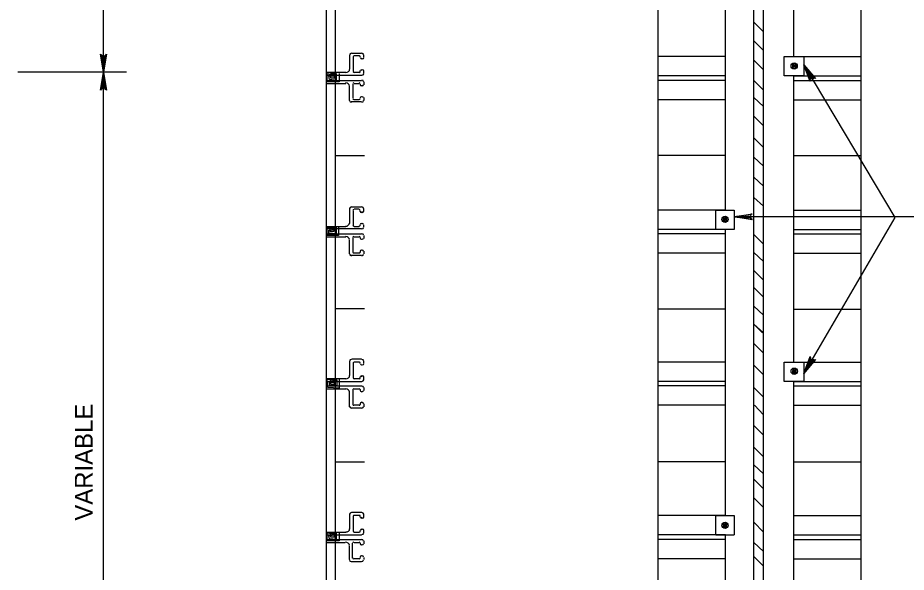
# Model space of a CAD drawing. Extents: x 647822 to 648727, y 298458 to 299646.
# Drawn here: x 648132.9 to 648281.8, y 299392.4 to 299485.4 of the extents above; entities that cross this region are included whole.
import ezdxf

# ---------------------------------------------------------------- set-up
doc = ezdxf.new("R2010")
doc.units = 0
doc.layers.add('2', color=7, linetype='Continuous')
doc.layers.add('3', color=7, linetype='Continuous')

# ---------------------------------------------------------------- blocks, each defined once
blk = doc.blocks.new('RARROW')
at = {"layer": '3'}
blk.add_lwpolyline([(-2.2695, 0.285), (-2.184875, 0.12075), (0, 0), (-2.2695, 0.285), (-2.38575, 0.384625), (0, 0), (-2.183125, -0.108), (-2.262875, -0.2705), (0, 0), (-2.38575, -0.379125), (-2.262875, -0.2705)], dxfattribs=at)

msp = doc.modelspace()

# ---------------------------------------------------------------- linework, layer by layer
at = {"layer": '2'}
for p, q in [((648147.25, 299476.23), (648147.25, 299540.48)), ((648184.63, 299335.43), (648184.63, 299539.1)), ((648186.13, 299335.43), (648186.13, 299539.1)), ((648240.25, 299335.47), (648240.25, 299538.73)), ((648256.25, 299335.47), (648256.25, 299538.73)), ((648257.88, 299335.47), (648257.88, 299538.73)), ((648274.25, 299335.47), (648274.25, 299538.73)), ((648263, 299478.85), (648263, 299522.23)), ((648251.5, 299453.1), (648251.5, 299500.6)), ((648257.88, 299482.98), (648256.25, 299484.6)), ((648257.88, 299479.85), (648256.25, 299481.48)), ((648188.5, 299479.1), (648188.5, 299476.73)), ((648190.5, 299479.35), (648188.88, 299479.35)), ((648189.13, 299478.85), (648189.13, 299476.35)), ((648190.13, 299478.98), (648189.25, 299478.98)), ((648190.25, 299478.73), (648190.25, 299478.85)), ((648190.63, 299478.48), (648190.5, 299478.48)), ((648190.88, 299478.73), (648190.88, 299479.1)), ((648251.5, 299478.85), (648240.25, 299478.85)), ((648257.88, 299476.6), (648256.25, 299478.23)), ((648261.38, 299478.85), (648264.63, 299478.85)), ((648261.38, 299475.6), (648261.38, 299478.85)), ((648263, 299478.85), (648274.25, 299478.85)), ((648263, 299478.85), (648263, 299478.85)), ((648264.63, 299478.85), (648264.63, 299475.6)), ((648190.25, 299476.35), (648190.25, 299476.48)), ((648190.5, 299476.6), (648190.63, 299476.6)), ((648190.88, 299475.98), (648190.88, 299476.48)), ((648264.63, 299477.48), (648279.88, 299451.85)), ((648151.13, 299476.23), (648132.88, 299476.23)), ((648147.25, 299335.48), (648147.25, 299476.23)), ((648184.63, 299476.23), (648187.88, 299476.23)), ((648184.63, 299475.73), (648190.5, 299475.73)), ((648189.25, 299476.23), (648190.13, 299476.23)), ((648251.5, 299475.6), (648240.25, 299475.6)), ((648264.63, 299475.6), (648261.38, 299475.6)), ((648263, 299475.73), (648263, 299475.73)), ((648263, 299475.6), (648274.25, 299475.6)), ((648263, 299427.6), (648263, 299475.6)), ((648184.63, 299474.85), (648190.5, 299474.85)), ((648184.63, 299474.35), (648187.88, 299474.35)), ((648188.5, 299471.48), (648188.5, 299473.85)), ((648189.13, 299471.85), (648189.13, 299474.23)), ((648189.25, 299474.35), (648190.13, 299474.35)), ((648190.25, 299474.23), (648190.25, 299474.1)), ((648190.5, 299473.98), (648190.63, 299473.98)), ((648190.88, 299474.6), (648190.88, 299474.1)), ((648251.5, 299474.85), (648240.25, 299474.85)), ((648257.88, 299473.23), (648256.25, 299474.85)), ((648263, 299474.85), (648274.25, 299474.85)), ((648190.25, 299471.98), (648190.25, 299471.85)), ((648190.63, 299472.1), (648190.5, 299472.1)), ((648190.88, 299471.98), (648190.88, 299471.48)), ((648257.88, 299470.48), (648256.25, 299471.98)), ((648190.5, 299471.23), (648188.75, 299471.23)), ((648190.13, 299471.6), (648189.25, 299471.6)), ((648251.5, 299471.6), (648240.25, 299471.6)), ((648263, 299471.6), (648274.25, 299471.6)), ((648257.88, 299467.23), (648256.25, 299468.85)), ((648257.88, 299463.6), (648256.25, 299465.23)), ((648186.13, 299462.23), (648191, 299462.23)), ((648251.5, 299462.23), (648240.25, 299462.23)), ((648257.88, 299460.48), (648256.25, 299461.98)), ((648263, 299462.23), (648274.25, 299462.23)), ((648257.88, 299457.1), (648256.25, 299458.6)), ((648257.88, 299453.73), (648256.25, 299455.23)), ((648188.5, 299453.35), (648188.5, 299450.85)), ((648190.5, 299453.6), (648188.75, 299453.6)), ((648189.13, 299452.98), (648189.13, 299450.48)), ((648190.13, 299453.23), (648189.25, 299453.23)), ((648190.25, 299452.85), (648190.25, 299452.98)), ((648190.63, 299452.73), (648190.5, 299452.73)), ((648190.88, 299452.85), (648190.88, 299453.35)), ((648251.5, 299453.1), (648240.25, 299453.1)), ((648249.88, 299453.1), (648253, 299453.1)), ((648249.88, 299449.85), (648249.88, 299453.1)), ((648251.5, 299453.1), (648251.5, 299453.1)), ((648253, 299453.1), (648253, 299449.85)), ((648263, 299453.1), (648274.25, 299453.1)), ((648280.13, 299451.98), (648253, 299451.98)), ((648279.88, 299451.85), (648264.63, 299425.69)), ((648313.17, 299451.98), (648279.88, 299451.98)), ((648184.63, 299450.35), (648187.88, 299450.35)), ((648184.63, 299449.98), (648190.5, 299449.98)), ((648189.25, 299450.35), (648190.13, 299450.35)), ((648190.25, 299450.48), (648190.25, 299450.6)), ((648190.5, 299450.85), (648190.63, 299450.85)), ((648190.88, 299450.23), (648190.88, 299450.6)), ((648251.5, 299449.85), (648240.25, 299449.85)), ((648253, 299449.85), (648249.88, 299449.85)), ((648251.5, 299401.85), (648251.5, 299449.85)), ((648263, 299449.85), (648274.25, 299449.85)), ((648184.63, 299449.1), (648190.5, 299449.1)), ((648184.63, 299448.6), (648187.88, 299448.6)), ((648188.5, 299445.73), (648188.5, 299448.1)), ((648189.13, 299445.98), (648189.13, 299448.48)), ((648189.25, 299448.6), (648190.13, 299448.6)), ((648190.25, 299448.48), (648190.25, 299448.35)), ((648190.5, 299448.23), (648190.63, 299448.23)), ((648190.88, 299448.85), (648190.88, 299448.35)), ((648251.5, 299449.1), (648240.25, 299449.1)), ((648257.88, 299447.35), (648256.25, 299448.98)), ((648263, 299449.1), (648274.25, 299449.1)), ((648190.5, 299445.48), (648188.75, 299445.48)), ((648190.13, 299445.85), (648189.25, 299445.85)), ((648190.25, 299446.23), (648190.25, 299445.98)), ((648190.63, 299446.35), (648190.5, 299446.35)), ((648190.88, 299446.23), (648190.88, 299445.73)), ((648251.5, 299445.85), (648240.25, 299445.85)), ((648257.88, 299444.48), (648256.25, 299445.98)), ((648263, 299445.85), (648274.25, 299445.85)), ((648257.88, 299441.35), (648256.25, 299442.98)), ((648257.88, 299438.48), (648256.25, 299440.1)), ((648186.13, 299436.6), (648191, 299436.6)), ((648251.5, 299436.48), (648240.25, 299436.48)), ((648257.88, 299435.48), (648256.25, 299436.98)), ((648263, 299436.48), (648274.25, 299436.48)), ((648257.75, 299432.48), (648256.25, 299433.98)), ((648257.88, 299432.48), (648256.25, 299433.98)), ((648257.88, 299429.1), (648256.25, 299430.73)), ((648188.5, 299427.73), (648188.5, 299425.35)), ((648190.5, 299428.1), (648188.88, 299428.1)), ((648189.13, 299427.48), (648189.13, 299424.98)), ((648190.13, 299427.6), (648189.25, 299427.6)), ((648190.25, 299427.35), (648190.25, 299427.48)), ((648190.88, 299427.35), (648190.88, 299427.73)), ((648251.38, 299427.6), (648240.25, 299427.6)), ((648261.38, 299427.6), (648264.63, 299427.6)), ((648261.38, 299424.35), (648261.38, 299427.6)), ((648263, 299427.6), (648274.25, 299427.6)), ((648264.63, 299427.6), (648264.63, 299424.35)), ((648190.63, 299427.1), (648190.5, 299427.1)), ((648257.88, 299425.48), (648256.25, 299427.1)), ((648184.63, 299424.85), (648187.88, 299424.85)), ((648184.63, 299424.35), (648190.5, 299424.35)), ((648189.25, 299424.85), (648190.13, 299424.85)), ((648190.25, 299424.98), (648190.25, 299425.1)), ((648190.5, 299425.23), (648190.63, 299425.23)), ((648190.88, 299424.6), (648190.88, 299425.1)), ((648251.38, 299424.35), (648240.25, 299424.35)), ((648264.63, 299424.35), (648261.38, 299424.35)), ((648263, 299424.35), (648274.25, 299424.35)), ((648263, 299376.1), (648263, 299424.35)), ((648184.63, 299423.6), (648190.5, 299423.6)), ((648184.63, 299423.1), (648187.88, 299423.1)), ((648189.13, 299420.48), (648189.13, 299422.98)), ((648189.25, 299423.1), (648190.13, 299423.1)), ((648190.25, 299422.98), (648190.25, 299422.85)), ((648190.88, 299423.35), (648190.88, 299422.85)), ((648251.38, 299423.6), (648240.25, 299423.6)), ((648257.88, 299421.73), (648256.25, 299423.35)), ((648263, 299423.6), (648274.25, 299423.6)), ((648188.5, 299420.1), (648188.5, 299422.6)), ((648190.5, 299422.6), (648190.63, 299422.6)), ((648190.5, 299419.85), (648188.75, 299419.85)), ((648190.13, 299420.35), (648189.25, 299420.35)), ((648190.25, 299420.6), (648190.25, 299420.48)), ((648190.63, 299420.85), (648190.5, 299420.85)), ((648190.88, 299420.6), (648190.88, 299420.1)), ((648251.38, 299420.35), (648240.25, 299420.35)), ((648257.88, 299418.73), (648256.38, 299420.35)), ((648263, 299420.35), (648274.25, 299420.35)), ((648257.88, 299415.35), (648256.25, 299416.98)), ((648257.88, 299411.73), (648256.25, 299413.35)), ((648186.13, 299410.85), (648191, 299410.85)), ((648251.5, 299410.85), (648240.25, 299410.85)), ((648263, 299410.85), (648274.25, 299410.85)), ((648257.88, 299408.85), (648256.25, 299410.35)), ((648257.88, 299406.35), (648256.25, 299407.98)), ((648257.88, 299403.23), (648256.25, 299404.85)), ((648188.5, 299402.1), (648188.5, 299399.6)), ((648190.5, 299402.35), (648188.88, 299402.35)), ((648190.88, 299401.6), (648190.88, 299402.1)), ((648189.13, 299401.73), (648189.13, 299399.23)), ((648190.13, 299401.85), (648189.25, 299401.85)), ((648190.25, 299401.6), (648190.25, 299401.73)), ((648190.63, 299401.48), (648190.5, 299401.48)), ((648251.5, 299401.85), (648240.25, 299401.85)), ((648249.88, 299401.85), (648253, 299401.85)), ((648249.88, 299398.6), (648249.88, 299401.85)), ((648251.5, 299401.85), (648251.5, 299401.85)), ((648253, 299401.85), (648253, 299398.6)), ((648257.88, 299399.1), (648256.25, 299400.73)), ((648263, 299401.85), (648274.25, 299401.85)), ((648184.63, 299399.1), (648187.88, 299399.1)), ((648189.25, 299399.1), (648190.13, 299399.1)), ((648190.25, 299399.23), (648190.25, 299399.35)), ((648190.5, 299399.6), (648190.63, 299399.6)), ((648190.88, 299398.98), (648190.88, 299399.35)), ((648184.63, 299398.6), (648190.5, 299398.6)), ((648184.63, 299397.85), (648190.5, 299397.85)), ((648190.88, 299397.6), (648190.88, 299397.1)), ((648251.5, 299398.6), (648240.25, 299398.6)), ((648251.5, 299397.85), (648240.25, 299397.85)), ((648251.5, 299398.6), (648249.88, 299398.6)), ((648249.88, 299398.6), (648253, 299398.6)), ((648251.5, 299398.6), (648251.5, 299398.6)), ((648251.5, 299352.1), (648251.5, 299398.6)), ((648263, 299398.6), (648274.25, 299398.6)), ((648263, 299397.85), (648274.25, 299397.85)), ((648184.63, 299397.35), (648187.75, 299397.35)), ((648188.5, 299394.48), (648188.5, 299396.85)), ((648189, 299394.73), (648189, 299397.23)), ((648189.25, 299397.35), (648190.13, 299397.35)), ((648190.25, 299397.23), (648190.25, 299397.1)), ((648190.5, 299396.98), (648190.63, 299396.98)), ((648257.88, 299395.85), (648256.25, 299397.35)), ((648190.13, 299394.6), (648189.25, 299394.6)), ((648190.25, 299394.85), (648190.25, 299394.73)), ((648190.63, 299395.1), (648190.5, 299395.1)), ((648190.88, 299394.85), (648190.88, 299394.48)), ((648251.5, 299394.6), (648240.25, 299394.6)), ((648257.88, 299393.35), (648256.25, 299394.98)), ((648263, 299394.6), (648274.25, 299394.6)), ((648190.5, 299394.1), (648188.75, 299394.1))]:
    msp.add_line(p, q, dxfattribs=at)
for points in [[(648262.88, 299477.6), (648262.75, 299477.35), (648262.75, 299476.98), (648263, 299476.85), (648263.25, 299476.98), (648263.38, 299477.23), (648263.38, 299477.48), (648263.25, 299477.6), (648263, 299477.6), (648262.88, 299477.35), (648262.88, 299477.23), (648262.88, 299477.1), (648263, 299477.1), (648263.13, 299477.23), (648263.25, 299477.35), (648263.13, 299477.48), (648263.13, 299477.35), (648263, 299477.23)], [(648186.75, 299475.98), (648186.75, 299474.6), (648184.75, 299474.6), (648184.75, 299475.98), (648186.25, 299475.73), (648186.25, 299475.85), (648186.25, 299474.85), (648185.13, 299474.98), (648185, 299475.6), (648185.88, 299475.6), (648186, 299475.23), (648185.38, 299475.23), (648185.38, 299475.98), (648186.25, 299475.98), (648186.25, 299475.85)], [(648251.25, 299451.85), (648251.13, 299451.6), (648251.13, 299451.35), (648251.38, 299451.1), (648251.63, 299451.23), (648251.75, 299451.48), (648251.75, 299451.73), (648251.63, 299451.85), (648251.5, 299451.85), (648251.25, 299451.6), (648251.25, 299451.48), (648251.25, 299451.35), (648251.38, 299451.35), (648251.5, 299451.48), (648251.63, 299451.6), (648251.63, 299451.73), (648251.5, 299451.6), (648251.38, 299451.48)], [(648186.63, 299450.23), (648186.63, 299448.85), (648184.75, 299448.85), (648184.75, 299450.23), (648186.25, 299449.98), (648186.25, 299450.1), (648186.25, 299449.1), (648185, 299449.23), (648185, 299449.73), (648185.88, 299449.85), (648185.88, 299449.48), (648185.25, 299449.48), (648185.25, 299450.23), (648186.25, 299450.23), (648186.25, 299450.1)], [(648262.88, 299426.48), (648262.75, 299426.1), (648262.75, 299425.85), (648263, 299425.73), (648263.25, 299425.73), (648263.38, 299425.98), (648263.38, 299426.23), (648263.25, 299426.48), (648263, 299426.35), (648262.88, 299426.1), (648262.88, 299425.98), (648262.88, 299425.85), (648263, 299425.85), (648263.13, 299425.98), (648263.25, 299426.1), (648263.13, 299426.23), (648263.13, 299426.1), (648263, 299425.98)], [(648186.75, 299424.73), (648186.75, 299423.23), (648184.88, 299423.35), (648184.75, 299424.73), (648186.25, 299424.48), (648186.38, 299424.6), (648186.38, 299423.6), (648185.13, 299423.6), (648185.13, 299424.23), (648185.88, 299424.23), (648186, 299423.85), (648185.38, 299423.85), (648185.38, 299424.73), (648186.25, 299424.73), (648186.25, 299424.48)], [(648251.25, 299400.6), (648251.13, 299400.23), (648251.13, 299399.98), (648251.38, 299399.85), (648251.63, 299399.98), (648251.75, 299400.23), (648251.75, 299400.48), (648251.63, 299400.6), (648251.5, 299400.48), (648251.25, 299400.23), (648251.25, 299400.1), (648251.25, 299400.1), (648251.38, 299399.98), (648251.5, 299400.23), (648251.63, 299400.23), (648251.63, 299400.48), (648251.5, 299400.35), (648251.38, 299400.1)], [(648186.75, 299398.98), (648186.75, 299397.6), (648184.75, 299397.6), (648184.75, 299398.98), (648186.25, 299398.73), (648186.25, 299398.85), (648186.25, 299397.85), (648185.13, 299397.98), (648185, 299398.48), (648185.88, 299398.6), (648186, 299398.23), (648185.38, 299398.23), (648185.38, 299398.98), (648186.25, 299398.98), (648186.25, 299398.85)]]:
    msp.add_lwpolyline(points, dxfattribs=at)
for centre in [(648263.03, 299477.28), (648251.44, 299451.53), (648263.04, 299426.07), (648251.44, 299400.23)]:
    msp.add_circle(centre, 0.525, dxfattribs=at)
for centre, major_axis, start_param, end_param in [((648188.84, 299479.14), (-0.327, 0), 4.712389, 6.283185), ((648190.56, 299479.14), (0.327, 0), 0, 1.570796), ((648189.25, 299478.81), (-0.163, 0), 4.712389, 6.283185), ((648190.14, 299478.81), (-0.163, 0), 3.141593, 4.712389), ((648190.56, 299478.68), (0.251, 0), 3.141593, 4.712389), ((648190.63, 299478.68), (0.251, 0), 4.712389, 6.283185), ((648187.86, 299476.69), (0.653, 0), 4.712389, 6.283185), ((648190.56, 299476.43), (-0.251, 0), 4.712389, 6.283185), ((648190.63, 299476.43), (0.251, 0), 0, 1.570796), ((648189.25, 299476.3), (0.163, 0), 3.141593, 4.712389), ((648190.14, 299476.3), (0.163, 0), 4.712389, 6.283185), ((648190.56, 299475.97), (0.327, 0), 4.712389, 6.283185), ((648187.83, 299473.89), (0.653, 0), 0, 1.570796), ((648189.22, 299474.29), (-0.163, 0), 4.712389, 6.283185), ((648190.12, 299474.29), (0.163, 0), 0, 1.570796), ((648190.53, 299474.16), (-0.251, 0), 0, 1.570796), ((648190.53, 299474.62), (0.327, 0), 0, 1.570796), ((648190.61, 299474.16), (0.251, 0), 4.712389, 6.283185), ((648190.53, 299471.91), (-0.251, 0), 4.712389, 6.283185), ((648190.61, 299471.91), (-0.251, 0), 3.141593, 4.712389), ((648188.81, 299471.45), (0.327, 0), 3.141593, 4.712389), ((648189.22, 299471.78), (-0.163, 0), 0, 1.570796), ((648190.12, 299471.78), (0.163, 0), 4.712389, 6.283185), ((648190.53, 299471.45), (0.327, 0), 4.712389, 6.283185), ((648188.81, 299453.36), (-0.327, 0), 4.712389, 6.283185), ((648189.22, 299453.03), (-0.163, 0), 4.712389, 6.283185), ((648190.12, 299453.03), (-0.163, 0), 3.141593, 4.712389), ((648190.53, 299452.9), (0.251, 0), 3.141593, 4.712389), ((648190.53, 299453.36), (0.327, 0), 0, 1.570796), ((648190.61, 299452.9), (0.251, 0), 4.712389, 6.283185), ((648187.83, 299450.91), (0.653, 0), 4.712389, 6.283185), ((648189.22, 299450.52), (0.163, 0), 3.141593, 4.712389), ((648190.12, 299450.52), (0.163, 0), 4.712389, 6.283185), ((648190.53, 299450.65), (-0.251, 0), 4.712389, 6.283185), ((648190.53, 299450.19), (0.327, 0), 4.712389, 6.283185), ((648190.61, 299450.65), (0.251, 0), 0, 1.570796), ((648187.83, 299448.14), (0.653, 0), 0, 1.570796), ((648189.22, 299448.54), (-0.163, 0), 4.712389, 6.283185), ((648190.12, 299448.54), (0.163, 0), 0, 1.570796), ((648190.53, 299448.41), (-0.251, 0), 0, 1.570796), ((648190.53, 299448.86), (0.327, 0), 0, 1.570796), ((648190.61, 299448.41), (0.251, 0), 4.712389, 6.283185), ((648188.81, 299445.7), (0.327, 0), 3.141593, 4.712389), ((648189.22, 299446.03), (-0.163, 0), 0, 1.570796), ((648190.12, 299446.03), (0.163, 0), 4.712389, 6.283185), ((648190.53, 299446.15), (-0.251, 0), 4.712389, 6.283185), ((648190.53, 299445.7), (0.327, 0), 4.712389, 6.283185), ((648190.61, 299446.15), (-0.251, 0), 3.141593, 4.712389), ((648188.84, 299427.79), (-0.327, 0), 4.712389, 6.283185), ((648189.25, 299427.45), (-0.163, 0), 4.712389, 6.283185), ((648190.14, 299427.45), (-0.163, 0), 3.141593, 4.712389), ((648190.56, 299427.33), (0.251, 0), 3.141593, 4.712389), ((648190.56, 299427.79), (0.327, 0), 0, 1.570796), ((648190.63, 299427.33), (0.251, 0), 4.712389, 6.283185), ((648187.86, 299425.34), (0.653, 0), 4.712389, 6.283185), ((648189.25, 299424.95), (0.163, 0), 3.141593, 4.712389), ((648190.14, 299424.95), (0.163, 0), 4.712389, 6.283185), ((648190.56, 299425.08), (-0.251, 0), 4.712389, 6.283185), ((648190.56, 299424.62), (0.327, 0), 4.712389, 6.283185), ((648190.63, 299425.08), (0.251, 0), 0, 1.570796), ((648187.83, 299422.59), (0.653, 0), 0, 1.570796), ((648189.22, 299422.99), (-0.163, 0), 4.712389, 6.283185), ((648190.12, 299422.99), (0.163, 0), 0, 1.570796), ((648190.53, 299422.86), (-0.251, 0), 0, 1.570796), ((648190.53, 299423.32), (0.327, 0), 0, 1.570796), ((648190.61, 299422.86), (0.251, 0), 4.712389, 6.283185), ((648188.81, 299420.15), (0.327, 0), 3.141593, 4.712389), ((648189.22, 299420.48), (-0.163, 0), 0, 1.570796), ((648190.12, 299420.48), (0.163, 0), 4.712389, 6.283185), ((648190.53, 299420.61), (-0.251, 0), 4.712389, 6.283185), ((648190.53, 299420.15), (0.327, 0), 4.712389, 6.283185), ((648190.61, 299420.61), (-0.251, 0), 3.141593, 4.712389), ((648188.84, 299402.08), (-0.327, 0), 4.712389, 6.283185), ((648190.56, 299402.08), (0.327, 0), 0, 1.570796), ((648189.25, 299401.75), (-0.163, 0), 4.712389, 6.283185), ((648190.14, 299401.75), (-0.163, 0), 3.141593, 4.712389), ((648190.56, 299401.63), (0.251, 0), 3.141593, 4.712389), ((648190.63, 299401.63), (0.251, 0), 4.712389, 6.283185), ((648187.86, 299399.64), (0.653, 0), 4.712389, 6.283185), ((648189.25, 299399.24), (0.163, 0), 3.141593, 4.712389), ((648190.14, 299399.24), (0.163, 0), 4.712389, 6.283185), ((648190.56, 299399.37), (-0.251, 0), 4.712389, 6.283185), ((648190.63, 299399.37), (0.251, 0), 0, 1.570796), ((648190.51, 299397.59), (0.327, 0), 0, 1.570796), ((648190.56, 299398.92), (0.327, 0), 4.712389, 6.283185), ((648187.81, 299396.87), (0.653, 0), 0, 1.570796), ((648189.19, 299397.26), (-0.163, 0), 4.712389, 6.283185), ((648190.09, 299397.26), (0.163, 0), 0, 1.570796), ((648190.51, 299397.13), (-0.251, 0), 0, 1.570796), ((648190.58, 299397.13), (0.251, 0), 4.712389, 6.283185), ((648189.19, 299394.75), (-0.163, 0), 0, 1.570796), ((648190.09, 299394.75), (0.163, 0), 4.712389, 6.283185), ((648190.51, 299394.88), (-0.251, 0), 4.712389, 6.283185), ((648190.58, 299394.88), (-0.251, 0), 3.141593, 4.712389), ((648188.79, 299394.42), (0.327, 0), 3.141593, 4.712389), ((648190.51, 299394.42), (0.327, 0), 4.712389, 6.283185)]:
    msp.add_ellipse(centre, major_axis=major_axis, ratio=0.806863, start_param=start_param, end_param=end_param, dxfattribs=at)

# ---------------------------------------------------------------- block references
at = {"layer": '2', "xscale": 1.2574347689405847}
for p, yscale, rotation in [((648147.25, 299476.23), 1.3092961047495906, -90.00000000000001), ((648264.63, 299477.48), 1.3092961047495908, 120.59122228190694), ((648147.25, 299476.23), 1.3092961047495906, 89.99999999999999), ((648253, 299451.98), 1.3092961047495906, 180), ((648264.63, 299425.69), 1.3092961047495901, -120.50632061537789)]:
    msp.add_blockref('RARROW', p, dxfattribs=dict(at, yscale=yscale, rotation=rotation))

# ---------------------------------------------------------------- texts
at = {"layer": '2'}
msp.add_text('VARIABLE', height=3, rotation=90, dxfattribs=at).set_placement((648145.45, 299401))

doc.saveas('drawing.dxf')
